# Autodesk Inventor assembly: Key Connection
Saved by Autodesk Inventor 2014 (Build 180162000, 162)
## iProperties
Created: 2010-12
Part Number: Key Connection
Document SubType Name: Assembly
Designer: Beta-8540w
ClientObjectVersion: 1
Author: Beta-8540w
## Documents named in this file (2)
- C:\Inventor 2014 Essentials\Assemblies\Chapter 08\c08-01\Design Accelerator\Key Connection1.iam
- C:\Inventor 2014 Essentials\Content Center Files\en-US\DIN 6885  A\DIN 6885 - A 4 x 4 x 12.ipt
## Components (1 placed, 1 different names)
1. DIN 6885 A A 4 x 4 x 12:1
